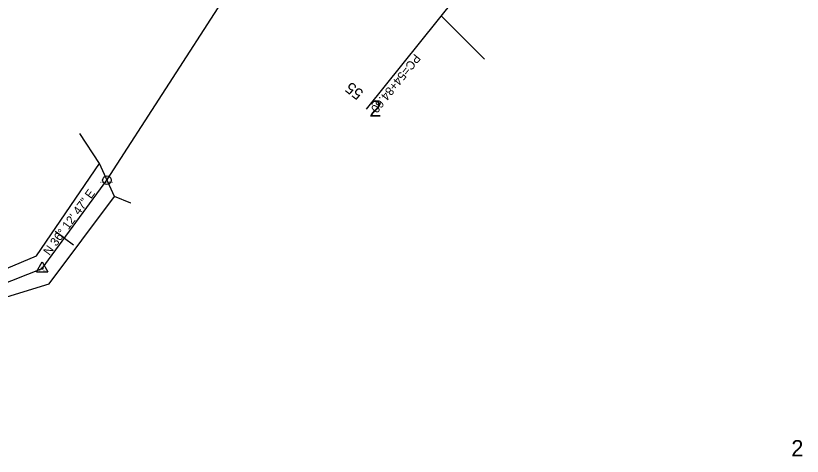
# Model space of a CAD drawing. Extents: x 2519952 to 2531965, y 848341 to 887632.
# Drawn here: x 2525961 to 2526510, y 850994 to 851302 of the extents above; entities that cross this region are included whole.
import ezdxf

# ---------------------------------------------------------------- set-up
doc = ezdxf.new("R2010")
doc.units = 0
for name, color, linetype in [('RD_EX_DV_Prop', 7, 'Continuous'), ('RD_EX_DV_TX_Prop', 7, 'Continuous'), ('RD_EX_H2O', 7, 'Continuous'), ('RD_EX_Misc', 7, 'Continuous'), ('RD_HC_Cl', 7, 'Continuous'), ('RD_HC_Data', 7, 'Continuous'), ('RD_HC_Data_Tic', 7, 'Continuous'), ('RD_HC_TX_Sta50', 7, 'Continuous'), ('RD_HC_txCode', 7, 'Continuous'), ('RD_SMD_Locator', 7, 'Continuous')]:
    doc.layers.add(name, color=color, linetype=linetype)

msp = doc.modelspace()

# ---------------------------------------------------------------- linework, layer by layer
at = {"layer": 'RD_EX_DV_Prop'}
for p, q in [((2526024.77, 851186.8), (2526149.82, 851380.73)), ((2526258.09, 851301.63), (2526288.29, 851271.38)), ((2525979.55, 851125.04), (2526024.77, 851186.8)), ((2525866.4, 851080.55), (2525979.55, 851125.04))]:
    msp.add_line(p, q, dxfattribs=at)
at = {"layer": 'RD_EX_H2O'}
for points in [[(2525863.08, 851085.28), (2525867.27, 851088.66), (2525883.49, 851094.37), (2525918.53, 851109.97), (2525975.54, 851133.87), (2526019.55, 851198.39)], [(2525921.38, 851095.03), (2525984.38, 851114.39), (2526029.94, 851175.31)]]:
    msp.add_lwpolyline(points, dxfattribs=at)
at = {"layer": 'RD_EX_Misc'}
msp.add_lwpolyline([(2526041.52, 851170.75), (2526029.94, 851175.31), (2526019.55, 851198.39), (2526005.82, 851219.28)], dxfattribs=at)
at = {"layer": 'RD_HC_Cl'}
for p, q in [((2525979.55, 851125.04), (2526024.77, 851186.8)), ((2525866.4, 851080.55), (2525979.55, 851125.04))]:
    msp.add_line(p, q, dxfattribs=at)
at = {"layer": 'RD_HC_Data'}
for p, q in [((2526278.74, 851327.37), (2526205.71, 851236.36)), ((2525975.58, 851122.75), (2525979.55, 851129.63)), ((2525979.55, 851129.63), (2525983.52, 851122.75)), ((2525975.58, 851122.75), (2525983.52, 851122.75))]:
    msp.add_line(p, q, dxfattribs=at)
for centre, radius in [((2526024.77, 851186.8), 3), ((2526024.77, 851186.8), 0.282), ((2525979.55, 851125.04), 0.529)]:
    msp.add_circle(centre, radius, dxfattribs=at)
at = {"layer": 'RD_HC_Data_Tic'}
for q in [(2525988.58, 851150.92), (2526001.49, 851141.47)]:
    msp.add_line((2525995.04, 851146.19), q, dxfattribs=at)
at = {"layer": 'RD_SMD_Locator'}
for centre in [(2526005.82, 851219.28), (2526019.55, 851198.39), (2526019.55, 851198.39), (2526024.77, 851186.8), (2526029.94, 851175.31), (2526029.94, 851175.31), (2526041.52, 851170.75), (2525975.54, 851133.87), (2525979.55, 851125.04), (2525984.38, 851114.39)]:
    msp.add_circle(centre, 0.001, dxfattribs=at)

# ---------------------------------------------------------------- texts
at = {"layer": 'RD_EX_DV_TX_Prop'}
for p in [(2526207.97, 851231.15), (2526502.57, 850993.84)]:
    msp.add_text('2', height=11.32, dxfattribs=at).set_placement(p)
at = {"layer": 'RD_HC_Data'}
for s, rotation, p in [('PC=54+84.60', 231.2529, (2526239.62, 851275.42)), ('N 36%%d 12\' 47" E', 53.787, (2525984.64, 851133.68))]:
    msp.add_text(s, height=6, rotation=rotation, dxfattribs=at).set_placement(p)
at = {"layer": 'RD_HC_TX_Sta50'}
msp.add_text('55', height=8, rotation=141.8357, dxfattribs=at).set_placement((2526204.48, 851248.47))
at = {"layer": 'RD_HC_txCode'}
for s, p in [('POT 15+50.33', (2526019.82, 851184.8)), ('43', (2526024.04, 851187.8)), ('42', (2525978.82, 851126.04)), ('PI 14+73.78', (2525975.77, 851123.04))]:
    msp.add_text(s, height=1, dxfattribs=at).set_placement(p)

doc.saveas('drawing.dxf')
